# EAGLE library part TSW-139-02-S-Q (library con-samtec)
THROUGH-HOLE .025" SQ POST HEADER Source: Samtec TSW.pdf
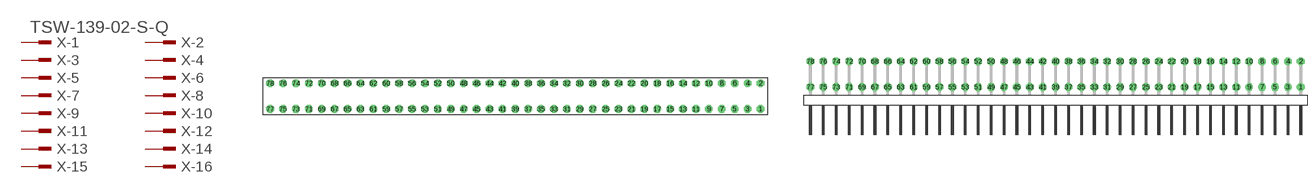
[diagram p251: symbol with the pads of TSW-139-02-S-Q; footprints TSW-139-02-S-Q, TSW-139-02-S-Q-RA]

Designator prefix X; gates -1=MPINV -2=MPIN -3=MPIN -4=MPIN -5=MPIN -6=MPIN -7=MPIN -8=MPIN -9=MPIN -10=MPIN -11=MPIN -12=MPIN -13=MPIN -14=MPIN -15=MPIN -16=MPIN -17=MPIN -18=MPIN -19=MPIN -20=MPIN -21=MPIN -22=MPIN -23=MPIN -24=MPIN -25=MPIN -26=MPIN -27=MPIN -28=MPIN -29=MPIN -30=MPIN -31=MPIN -32=MPIN -33=MPIN -34=MPIN -35=MPIN -36=MPIN -37=MPIN -38=MPIN -39=MPIN -40=MPIN -41=MPIN -42=MPIN -43=MPIN -44=MPIN -45=MPIN -46=MPIN -47=MPIN -48=MPIN -49=MPIN -50=MPIN -51=MPIN -52=MPIN -53=MPIN -54=MPIN -55=MPIN -56=MPIN -57=MPIN -58=MPIN -59=MPIN -60=MPIN -61=MPIN -62=MPIN -63=MPIN -64=MPIN -65=MPIN -66=MPIN -67=MPIN -68=MPIN -69=MPIN -70=MPIN -71=MPIN -72=MPIN -73=MPIN -74=MPIN -75=MPIN -76=MPIN -77=MPIN -78=MPIN

## TSW-139-02-S-Q (OC_FARNELL: unknown; OC_NEWARK: unknown)  [TSW-139-02-S-Q]
1  -1:1  pas
2  -2:1  pas
3  -3:1  pas
4  -4:1  pas
5  -5:1  pas
6  -6:1  pas
7  -7:1  pas
8  -8:1  pas
9  -9:1  pas
10  -10:1  pas
11  -11:1  pas
12  -12:1  pas
13  -13:1  pas
14  -14:1  pas
15  -15:1  pas
16  -16:1  pas
17  -17:1  pas
18  -18:1  pas
19  -19:1  pas
20  -20:1  pas
21  -21:1  pas
22  -22:1  pas
23  -23:1  pas
24  -24:1  pas
25  -25:1  pas
26  -26:1  pas
27  -27:1  pas
28  -28:1  pas
29  -29:1  pas
30  -30:1  pas
31  -31:1  pas
32  -32:1  pas
33  -33:1  pas
34  -34:1  pas
35  -35:1  pas
36  -36:1  pas
37  -37:1  pas
38  -38:1  pas
39  -39:1  pas
40  -40:1  pas
41  -41:1  pas
42  -42:1  pas
43  -43:1  pas
44  -44:1  pas
45  -45:1  pas
46  -46:1  pas
47  -47:1  pas
48  -48:1  pas
49  -49:1  pas
50  -50:1  pas
51  -51:1  pas
52  -52:1  pas
53  -53:1  pas
54  -54:1  pas
55  -55:1  pas
56  -56:1  pas
57  -57:1  pas
58  -58:1  pas
59  -59:1  pas
60  -60:1  pas
61  -61:1  pas
62  -62:1  pas
63  -63:1  pas
64  -64:1  pas
65  -65:1  pas
66  -66:1  pas
67  -67:1  pas
68  -68:1  pas
69  -69:1  pas
70  -70:1  pas
71  -71:1  pas
72  -72:1  pas
73  -73:1  pas
74  -74:1  pas
75  -75:1  pas
76  -76:1  pas
77  -77:1  pas
78  -78:1  pas

## TSW-139-02-S-Q-RA (OC_FARNELL: unknown; OC_NEWARK: unknown)  [TSW-139-02-S-Q-RA]
Pads as for TSW-139-02-S-Q

## Footprint TSW-139-02-S-Q (pad centres in mm)
THROUGH-HOLE .025" SQ POST HEADER Source: Samtec TSW.pdf
drill 1 pad 1.5 octagon: 1 48.26,-2.54; 2 48.26,2.54; 3 45.72,-2.54; 4 45.72,2.54; 5 43.18,-2.54; 6 43.18,2.54; 7 40.64,-2.54; 8 40.64,2.54; 9 38.1,-2.54; 10 38.1,2.54; 11 35.56,-2.54; 12 35.56,2.54; 13 33.02,-2.54; 14 33.02,2.54; 15 30.48,-2.54; 16 30.48,2.54; 17 27.94,-2.54; 18 27.94,2.54; 19 25.4,-2.54; 20 25.4,2.54; 21 22.86,-2.54; 22 22.86,2.54; 23 20.32,-2.54; 24 20.32,2.54; 25 17.78,-2.54; 26 17.78,2.54; 27 15.24,-2.54; 28 15.24,2.54; 29 12.7,-2.54; 30 12.7,2.54; 31 10.16,-2.54; 32 10.16,2.54; 33 7.62,-2.54; 34 7.62,2.54; 35 5.08,-2.54; 36 5.08,2.54; 37 2.54,-2.54; 38 2.54,2.54; 39 0,-2.54; 40 0,2.54; 41 -2.54,-2.54; 42 -2.54,2.54; 43 -5.08,-2.54; 44 -5.08,2.54; 45 -7.62,-2.54; 46 -7.62,2.54; 47 -10.16,-2.54; 48 -10.16,2.54; 49 -12.7,-2.54; 50 -12.7,2.54; 51 -15.24,-2.54; 52 -15.24,2.54; 53 -17.78,-2.54; 54 -17.78,2.54; 55 -20.32,-2.54; 56 -20.32,2.54; 57 -22.86,-2.54; 58 -22.86,2.54; 59 -25.4,-2.54; 60 -25.4,2.54; 61 -27.94,-2.54; 62 -27.94,2.54; 63 -30.48,-2.54; 64 -30.48,2.54; 65 -33.02,-2.54; 66 -33.02,2.54; 67 -35.56,-2.54; 68 -35.56,2.54; 69 -38.1,-2.54; 70 -38.1,2.54; 71 -40.64,-2.54; 72 -40.64,2.54; 73 -43.18,-2.54; 74 -43.18,2.54; 75 -45.72,-2.54; 76 -45.72,2.54; 77 -48.26,-2.54; 78 -48.26,2.54

## Footprint TSW-139-02-S-Q-RA (pad centres in mm)
THROUGH-HOLE .025" SQ POST HEADER Source: Samtec TSW.pdf
drill 1 pad 1.5 octagon: 1 48.26,1.524; 2 48.26,6.604; 3 45.72,1.524; 4 45.72,6.604; 5 43.18,1.524; 6 43.18,6.604; 7 40.64,1.524; 8 40.64,6.604; 9 38.1,1.524; 10 38.1,6.604; 11 35.56,1.524; 12 35.56,6.604; 13 33.02,1.524; 14 33.02,6.604; 15 30.48,1.524; 16 30.48,6.604; 17 27.94,1.524; 18 27.94,6.604; 19 25.4,1.524; 20 25.4,6.604; 21 22.86,1.524; 22 22.86,6.604; 23 20.32,1.524; 24 20.32,6.604; 25 17.78,1.524; 26 17.78,6.604; 27 15.24,1.524; 28 15.24,6.604; 29 12.7,1.524; 30 12.7,6.604; 31 10.16,1.524; 32 10.16,6.604; 33 7.62,1.524; 34 7.62,6.604; 35 5.08,1.524; 36 5.08,6.604; 37 2.54,1.524; 38 2.54,6.604; 39 0,1.524; 40 0,6.604; 41 -2.54,1.524; 42 -2.54,6.604; 43 -5.08,1.524; 44 -5.08,6.604; 45 -7.62,1.524; 46 -7.62,6.604; 47 -10.16,1.524; 48 -10.16,6.604; 49 -12.7,1.524; 50 -12.7,6.604; 51 -15.24,1.524; 52 -15.24,6.604; 53 -17.78,1.524; 54 -17.78,6.604; 55 -20.32,1.524; 56 -20.32,6.604; 57 -22.86,1.524; 58 -22.86,6.604; 59 -25.4,1.524; 60 -25.4,6.604; 61 -27.94,1.524; 62 -27.94,6.604; 63 -30.48,1.524; 64 -30.48,6.604; 65 -33.02,1.524; 66 -33.02,6.604; 67 -35.56,1.524; 68 -35.56,6.604; 69 -38.1,1.524; 70 -38.1,6.604; 71 -40.64,1.524; 72 -40.64,6.604; 73 -43.18,1.524; 74 -43.18,6.604; 75 -45.72,1.524; 76 -45.72,6.604; 77 -48.26,1.524; 78 -48.26,6.604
